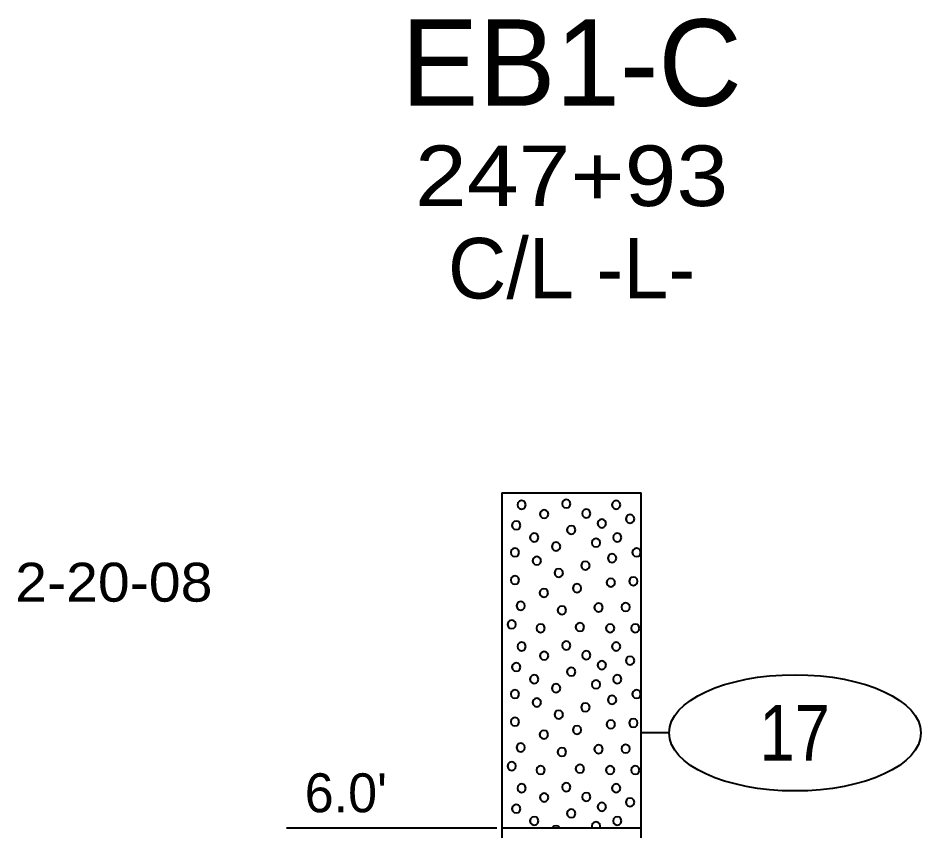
# Model space of a CAD drawing. Extents: x -76 to 974, y -1080 to -735.
# Drawn here: x -20.21 to -4.02, y -772.06 to -757.49 of the extents above; entities that cross this region are included whole.
import ezdxf
from ezdxf.enums import TextEntityAlignment as Align

# ---------------------------------------------------------------- set-up
doc = ezdxf.new("R2010")
doc.units = 0
doc.header["$LTSCALE"] = 0.36
doc.layers.add('27', color=7, linetype='Continuous', lineweight=40)

msp = doc.modelspace()

# ---------------------------------------------------------------- linework, layer by layer
at = {"layer": '27'}
for p, q in [((-11.5338, -766.0053), (-11.5338, -772.0053)), ((-11.5338, -766.0053), (-9.0338, -766.0053)), ((-9.0338, -772.0053), (-9.0338, -766.0053)), ((-8.5338, -770.3053), (-9.0338, -770.3053)), ((-15.39, -772.0053), (-11.6226, -772.0053)), ((-11.5338, -772.0053), (-9.0338, -772.0053)), ((-11.5338, -772.0053), (-11.5338, -778.0053)), ((-9.0338, -778.0053), (-9.0338, -772.0053))]:
    msp.add_line(p, q, dxfattribs=at)
for points in [[(-11.1019, -766.2179), (-11.1121, -766.1798), (-11.14, -766.1519), (-11.1781, -766.1417), (-11.2162, -766.1519), (-11.244, -766.1798), (-11.2543, -766.2179), (-11.244, -766.256), (-11.2162, -766.2839), (-11.1781, -766.2941), (-11.14, -766.2839), (-11.1121, -766.256)], [(-10.3009, -766.1983), (-10.3111, -766.1602), (-10.339, -766.1323), (-10.3771, -766.1221), (-10.4152, -766.1323), (-10.4431, -766.1602), (-10.4533, -766.1983), (-10.4431, -766.2364), (-10.4152, -766.2643), (-10.3771, -766.2745), (-10.339, -766.2643), (-10.3111, -766.2364)], [(-9.4072, -766.218), (-9.4174, -766.1799), (-9.4453, -766.152), (-9.4834, -766.1418), (-9.5215, -766.152), (-9.5494, -766.1799), (-9.5596, -766.218), (-9.5494, -766.2561), (-9.5215, -766.284), (-9.4834, -766.2942), (-9.4453, -766.284), (-9.4174, -766.2561)], [(-10.6969, -766.3832), (-10.7071, -766.3451), (-10.735, -766.3172), (-10.7731, -766.307), (-10.8112, -766.3172), (-10.8391, -766.3451), (-10.8493, -766.3832), (-10.8391, -766.4213), (-10.8112, -766.4492), (-10.7731, -766.4594), (-10.735, -766.4492), (-10.7071, -766.4213)], [(-9.9418, -766.3742), (-9.952, -766.3361), (-9.9799, -766.3082), (-10.018, -766.298), (-10.0561, -766.3082), (-10.084, -766.3361), (-10.0942, -766.3742), (-10.084, -766.4123), (-10.0561, -766.4402), (-10.018, -766.4504), (-9.9799, -766.4402), (-9.952, -766.4123)], [(-9.1564, -766.4701), (-9.1666, -766.432), (-9.1945, -766.4041), (-9.2326, -766.3939), (-9.2707, -766.4041), (-9.2986, -766.432), (-9.3088, -766.4701), (-9.2986, -766.5082), (-9.2707, -766.5361), (-9.2326, -766.5463), (-9.1945, -766.5361), (-9.1666, -766.5082)], [(-11.198, -766.5858), (-11.2082, -766.5477), (-11.2361, -766.5198), (-11.2742, -766.5096), (-11.3123, -766.5198), (-11.3402, -766.5477), (-11.3504, -766.5858), (-11.3402, -766.6239), (-11.3123, -766.6518), (-11.2742, -766.662), (-11.2361, -766.6518), (-11.2082, -766.6239)], [(-9.6636, -766.5514), (-9.6738, -766.5133), (-9.7017, -766.4854), (-9.7398, -766.4752), (-9.7779, -766.4854), (-9.8058, -766.5133), (-9.816, -766.5514), (-9.8058, -766.5895), (-9.7779, -766.6174), (-9.7398, -766.6276), (-9.7017, -766.6174), (-9.6738, -766.5895)], [(-10.8751, -766.8044), (-10.8853, -766.7663), (-10.9132, -766.7384), (-10.9513, -766.7282), (-10.9894, -766.7384), (-11.0173, -766.7663), (-11.0275, -766.8044), (-11.0173, -766.8425), (-10.9894, -766.8704), (-10.9513, -766.8806), (-10.9132, -766.8704), (-10.8853, -766.8425)], [(-10.2119, -766.669), (-10.2222, -766.6309), (-10.25, -766.603), (-10.2881, -766.5928), (-10.3262, -766.603), (-10.3541, -766.6309), (-10.3643, -766.669), (-10.3541, -766.7071), (-10.3262, -766.735), (-10.2881, -766.7452), (-10.25, -766.735), (-10.2222, -766.7071)], [(-9.3865, -766.8044), (-9.3967, -766.7663), (-9.4246, -766.7384), (-9.4627, -766.7282), (-9.5008, -766.7384), (-9.5287, -766.7663), (-9.5389, -766.8044), (-9.5287, -766.8425), (-9.5008, -766.8704), (-9.4627, -766.8806), (-9.4246, -766.8704), (-9.3967, -766.8425)], [(-10.4836, -766.9659), (-10.4938, -766.9278), (-10.5217, -766.8999), (-10.5598, -766.8897), (-10.5979, -766.8999), (-10.6258, -766.9278), (-10.636, -766.9659), (-10.6258, -767.004), (-10.5979, -767.0319), (-10.5598, -767.0421), (-10.5217, -767.0319), (-10.4938, -767.004)], [(-9.7678, -766.8972), (-9.7781, -766.8591), (-9.8059, -766.8312), (-9.844, -766.821), (-9.8821, -766.8312), (-9.91, -766.8591), (-9.9202, -766.8972), (-9.91, -766.9353), (-9.8821, -766.9632), (-9.844, -766.9734), (-9.8059, -766.9632), (-9.7781, -766.9353)], [(-11.2209, -767.0701), (-11.2311, -767.032), (-11.259, -767.0041), (-11.2971, -766.9939), (-11.3352, -767.0041), (-11.3631, -767.032), (-11.3733, -767.0701), (-11.3631, -767.1082), (-11.3352, -767.1361), (-11.2971, -767.1463), (-11.259, -767.1361), (-11.2311, -767.1082)], [(-9.0407, -767.0701), (-9.0509, -767.032), (-9.0788, -767.0041), (-9.1169, -766.9939), (-9.155, -767.0041), (-9.1829, -767.032), (-9.1931, -767.0701), (-9.1829, -767.1082), (-9.155, -767.1361), (-9.1169, -767.1463), (-9.0788, -767.1361), (-9.0509, -767.1082)], [(-10.8294, -767.2201), (-10.8396, -767.182), (-10.8675, -767.1541), (-10.9056, -767.1439), (-10.9437, -767.1541), (-10.9715, -767.182), (-10.9818, -767.2201), (-10.9715, -767.2582), (-10.9437, -767.2861), (-10.9056, -767.2963), (-10.8675, -767.2861), (-10.8396, -767.2582)], [(-9.4793, -767.1744), (-9.4895, -767.1363), (-9.5174, -767.1084), (-9.5555, -767.0982), (-9.5936, -767.1084), (-9.6215, -767.1363), (-9.6317, -767.1744), (-9.6215, -767.2125), (-9.5936, -767.2404), (-9.5555, -767.2506), (-9.5174, -767.2404), (-9.4895, -767.2125)], [(-10.4353, -767.4388), (-10.4455, -767.4007), (-10.4734, -767.3728), (-10.5115, -767.3626), (-10.5496, -767.3728), (-10.5775, -767.4007), (-10.5877, -767.4388), (-10.5775, -767.4769), (-10.5496, -767.5048), (-10.5115, -767.515), (-10.4734, -767.5048), (-10.4455, -767.4769)], [(-9.9573, -767.3078), (-9.9675, -767.2697), (-9.9954, -767.2419), (-10.0335, -767.2316), (-10.0716, -767.2419), (-10.0995, -767.2697), (-10.1097, -767.3078), (-10.0995, -767.3459), (-10.0716, -767.3738), (-10.0335, -767.384), (-9.9954, -767.3738), (-9.9675, -767.3459)], [(-11.2209, -767.5659), (-11.2311, -767.5278), (-11.259, -767.4999), (-11.2971, -767.4897), (-11.3352, -767.4999), (-11.3631, -767.5278), (-11.3733, -767.5659), (-11.3631, -767.604), (-11.3352, -767.6319), (-11.2971, -767.6421), (-11.259, -767.6319), (-11.2311, -767.604)], [(-9.5021, -767.613), (-9.5124, -767.5749), (-9.5402, -767.547), (-9.5783, -767.5368), (-9.6164, -767.547), (-9.6443, -767.5749), (-9.6545, -767.613), (-9.6443, -767.6511), (-9.6164, -767.6789), (-9.5783, -767.6892), (-9.5402, -767.6789), (-9.5124, -767.6511)], [(-9.0979, -767.5888), (-9.1081, -767.5507), (-9.136, -767.5228), (-9.1741, -767.5126), (-9.2122, -767.5228), (-9.2401, -767.5507), (-9.2503, -767.5888), (-9.2401, -767.6269), (-9.2122, -767.6548), (-9.1741, -767.665), (-9.136, -767.6548), (-9.1081, -767.6269)], [(-10.1073, -767.7134), (-10.1175, -767.6753), (-10.1454, -767.6474), (-10.1835, -767.6372), (-10.2216, -767.6474), (-10.2495, -767.6753), (-10.2597, -767.7134), (-10.2495, -767.7515), (-10.2216, -767.7794), (-10.1835, -767.7896), (-10.1454, -767.7794), (-10.1175, -767.7515)], [(-10.7022, -767.7973), (-10.7124, -767.7592), (-10.7403, -767.7313), (-10.7784, -767.7211), (-10.8165, -767.7313), (-10.8444, -767.7592), (-10.8546, -767.7973), (-10.8444, -767.8354), (-10.8165, -767.8633), (-10.7784, -767.8735), (-10.7403, -767.8633), (-10.7124, -767.8354)], [(-11.1179, -768.0287), (-11.1281, -767.9906), (-11.156, -767.9627), (-11.1941, -767.9525), (-11.2322, -767.9627), (-11.2601, -767.9906), (-11.2703, -768.0287), (-11.2601, -768.0668), (-11.2322, -768.0946), (-11.1941, -768.1049), (-11.156, -768.0946), (-11.1281, -768.0668)], [(-9.7221, -768.0579), (-9.7323, -768.0198), (-9.7602, -767.9919), (-9.7983, -767.9817), (-9.8364, -767.9919), (-9.8643, -768.0198), (-9.8745, -768.0579), (-9.8643, -768.096), (-9.8364, -768.1239), (-9.7983, -768.1341), (-9.7602, -768.1239), (-9.7323, -768.096)], [(-9.2365, -768.0503), (-9.2467, -768.0122), (-9.2746, -767.9843), (-9.3127, -767.9741), (-9.3508, -767.9843), (-9.3786, -768.0122), (-9.3889, -768.0503), (-9.3786, -768.0884), (-9.3508, -768.1163), (-9.3127, -768.1265), (-9.2746, -768.1163), (-9.2467, -768.0884)], [(-10.3793, -768.1087), (-10.3895, -768.0706), (-10.4174, -768.0428), (-10.4555, -768.0325), (-10.4936, -768.0428), (-10.5215, -768.0706), (-10.5317, -768.1087), (-10.5215, -768.1468), (-10.4936, -768.1747), (-10.4555, -768.1849), (-10.4174, -768.1747), (-10.3895, -768.1468)], [(-11.2794, -768.3617), (-11.2896, -768.3236), (-11.3175, -768.2957), (-11.3556, -768.2855), (-11.3937, -768.2957), (-11.4216, -768.3236), (-11.4318, -768.3617), (-11.4216, -768.3998), (-11.3937, -768.4277), (-11.3556, -768.4379), (-11.3175, -768.4277), (-11.2896, -768.3998)], [(-10.0564, -768.4088), (-10.0666, -768.3707), (-10.0945, -768.3428), (-10.1326, -768.3326), (-10.1707, -768.3428), (-10.1986, -768.3707), (-10.2088, -768.4088), (-10.1986, -768.4469), (-10.1707, -768.4748), (-10.1326, -768.485), (-10.0945, -768.4748), (-10.0666, -768.4469)], [(-10.7607, -768.4316), (-10.7709, -768.3935), (-10.7988, -768.3657), (-10.8369, -768.3554), (-10.875, -768.3657), (-10.9029, -768.3935), (-10.9131, -768.4316), (-10.9029, -768.4697), (-10.875, -768.4976), (-10.8369, -768.5078), (-10.7988, -768.4976), (-10.7709, -768.4697)], [(-9.5136, -768.4316), (-9.5238, -768.3935), (-9.5517, -768.3657), (-9.5898, -768.3554), (-9.6279, -768.3657), (-9.6558, -768.3935), (-9.666, -768.4316), (-9.6558, -768.4697), (-9.6279, -768.4976), (-9.5898, -768.5078), (-9.5517, -768.4976), (-9.5238, -768.4697)], [(-9.0636, -768.4316), (-9.0738, -768.3935), (-9.1017, -768.3657), (-9.1398, -768.3554), (-9.1779, -768.3657), (-9.2058, -768.3935), (-9.216, -768.4316), (-9.2058, -768.4697), (-9.1779, -768.4976), (-9.1398, -768.5078), (-9.1017, -768.4976), (-9.0738, -768.4697)], [(-10.3009, -768.7383), (-10.3111, -768.7002), (-10.339, -768.6723), (-10.3771, -768.6621), (-10.4152, -768.6723), (-10.4431, -768.7002), (-10.4533, -768.7383), (-10.4431, -768.7764), (-10.4152, -768.8043), (-10.3771, -768.8145), (-10.339, -768.8043), (-10.3111, -768.7764)], [(-11.1019, -768.7579), (-11.1121, -768.7198), (-11.14, -768.6919), (-11.1781, -768.6817), (-11.2162, -768.6919), (-11.244, -768.7198), (-11.2543, -768.7579), (-11.244, -768.796), (-11.2162, -768.8239), (-11.1781, -768.8341), (-11.14, -768.8239), (-11.1121, -768.796)], [(-9.4072, -768.758), (-9.4174, -768.7199), (-9.4453, -768.692), (-9.4834, -768.6818), (-9.5215, -768.692), (-9.5494, -768.7199), (-9.5596, -768.758), (-9.5494, -768.7961), (-9.5215, -768.824), (-9.4834, -768.8342), (-9.4453, -768.824), (-9.4174, -768.7961)], [(-10.6969, -768.9232), (-10.7071, -768.8851), (-10.735, -768.8572), (-10.7731, -768.847), (-10.8112, -768.8572), (-10.8391, -768.8851), (-10.8493, -768.9232), (-10.8391, -768.9613), (-10.8112, -768.9892), (-10.7731, -768.9994), (-10.735, -768.9892), (-10.7071, -768.9613)], [(-9.9418, -768.9142), (-9.952, -768.8761), (-9.9799, -768.8482), (-10.018, -768.838), (-10.0561, -768.8482), (-10.084, -768.8761), (-10.0942, -768.9142), (-10.084, -768.9523), (-10.0561, -768.9802), (-10.018, -768.9904), (-9.9799, -768.9802), (-9.952, -768.9523)], [(-9.1564, -769.0101), (-9.1666, -768.972), (-9.1945, -768.9441), (-9.2326, -768.9339), (-9.2707, -768.9441), (-9.2986, -768.972), (-9.3088, -769.0101), (-9.2986, -769.0482), (-9.2707, -769.0761), (-9.2326, -769.0863), (-9.1945, -769.0761), (-9.1666, -769.0482)], [(-11.198, -769.1258), (-11.2082, -769.0877), (-11.2361, -769.0598), (-11.2742, -769.0496), (-11.3123, -769.0598), (-11.3402, -769.0877), (-11.3504, -769.1258), (-11.3402, -769.1639), (-11.3123, -769.1918), (-11.2742, -769.202), (-11.2361, -769.1918), (-11.2082, -769.1639)], [(-10.2119, -769.209), (-10.2222, -769.1709), (-10.25, -769.143), (-10.2881, -769.1328), (-10.3262, -769.143), (-10.3541, -769.1709), (-10.3643, -769.209), (-10.3541, -769.2471), (-10.3262, -769.275), (-10.2881, -769.2852), (-10.25, -769.275), (-10.2222, -769.2471)], [(-9.6636, -769.0914), (-9.6738, -769.0533), (-9.7017, -769.0254), (-9.7398, -769.0152), (-9.7779, -769.0254), (-9.8058, -769.0533), (-9.816, -769.0914), (-9.8058, -769.1295), (-9.7779, -769.1574), (-9.7398, -769.1676), (-9.7017, -769.1574), (-9.6738, -769.1295)], [(-10.8751, -769.3444), (-10.8853, -769.3063), (-10.9132, -769.2784), (-10.9513, -769.2682), (-10.9894, -769.2784), (-11.0173, -769.3063), (-11.0275, -769.3444), (-11.0173, -769.3825), (-10.9894, -769.4104), (-10.9513, -769.4206), (-10.9132, -769.4104), (-10.8853, -769.3825)], [(-9.3865, -769.3444), (-9.3967, -769.3063), (-9.4246, -769.2784), (-9.4627, -769.2682), (-9.5008, -769.2784), (-9.5287, -769.3063), (-9.5389, -769.3444), (-9.5287, -769.3825), (-9.5008, -769.4104), (-9.4627, -769.4206), (-9.4246, -769.4104), (-9.3967, -769.3825)], [(-10.4836, -769.5059), (-10.4938, -769.4678), (-10.5217, -769.4399), (-10.5598, -769.4297), (-10.5979, -769.4399), (-10.6258, -769.4678), (-10.636, -769.5059), (-10.6258, -769.544), (-10.5979, -769.5719), (-10.5598, -769.5821), (-10.5217, -769.5719), (-10.4938, -769.544)], [(-9.7678, -769.4372), (-9.7781, -769.3991), (-9.8059, -769.3712), (-9.844, -769.361), (-9.8821, -769.3712), (-9.91, -769.3991), (-9.9202, -769.4372), (-9.91, -769.4753), (-9.8821, -769.5032), (-9.844, -769.5134), (-9.8059, -769.5032), (-9.7781, -769.4753)], [(-11.2209, -769.6101), (-11.2311, -769.572), (-11.259, -769.5441), (-11.2971, -769.5339), (-11.3352, -769.5441), (-11.3631, -769.572), (-11.3733, -769.6101), (-11.3631, -769.6482), (-11.3352, -769.6761), (-11.2971, -769.6863), (-11.259, -769.6761), (-11.2311, -769.6482)], [(-9.4793, -769.7144), (-9.4895, -769.6763), (-9.5174, -769.6484), (-9.5555, -769.6382), (-9.5936, -769.6484), (-9.6215, -769.6763), (-9.6317, -769.7144), (-9.6215, -769.7525), (-9.5936, -769.7804), (-9.5555, -769.7906), (-9.5174, -769.7804), (-9.4895, -769.7525)], [(-9.0407, -769.6101), (-9.0509, -769.572), (-9.0788, -769.5441), (-9.1169, -769.5339), (-9.155, -769.5441), (-9.1829, -769.572), (-9.1931, -769.6101), (-9.1829, -769.6482), (-9.155, -769.6761), (-9.1169, -769.6863), (-9.0788, -769.6761), (-9.0509, -769.6482)], [(-10.8294, -769.7601), (-10.8396, -769.722), (-10.8675, -769.6941), (-10.9056, -769.6839), (-10.9437, -769.6941), (-10.9715, -769.722), (-10.9818, -769.7601), (-10.9715, -769.7982), (-10.9437, -769.8261), (-10.9056, -769.8363), (-10.8675, -769.8261), (-10.8396, -769.7982)], [(-9.9573, -769.8478), (-9.9675, -769.8097), (-9.9954, -769.7819), (-10.0335, -769.7716), (-10.0716, -769.7819), (-10.0995, -769.8097), (-10.1097, -769.8478), (-10.0995, -769.8859), (-10.0716, -769.9138), (-10.0335, -769.924), (-9.9954, -769.9138), (-9.9675, -769.8859)], [(-10.4353, -769.9788), (-10.4455, -769.9407), (-10.4734, -769.9128), (-10.5115, -769.9026), (-10.5496, -769.9128), (-10.5775, -769.9407), (-10.5877, -769.9788), (-10.5775, -770.0169), (-10.5496, -770.0448), (-10.5115, -770.055), (-10.4734, -770.0448), (-10.4455, -770.0169)], [(-11.2209, -770.1059), (-11.2311, -770.0678), (-11.259, -770.0399), (-11.2971, -770.0297), (-11.3352, -770.0399), (-11.3631, -770.0678), (-11.3733, -770.1059), (-11.3631, -770.144), (-11.3352, -770.1719), (-11.2971, -770.1821), (-11.259, -770.1719), (-11.2311, -770.144)], [(-9.5021, -770.153), (-9.5124, -770.1149), (-9.5402, -770.087), (-9.5783, -770.0768), (-9.6164, -770.087), (-9.6443, -770.1149), (-9.6545, -770.153), (-9.6443, -770.1911), (-9.6164, -770.2189), (-9.5783, -770.2292), (-9.5402, -770.2189), (-9.5124, -770.1911)], [(-9.0979, -770.1288), (-9.1081, -770.0907), (-9.136, -770.0628), (-9.1741, -770.0526), (-9.2122, -770.0628), (-9.2401, -770.0907), (-9.2503, -770.1288), (-9.2401, -770.1669), (-9.2122, -770.1948), (-9.1741, -770.205), (-9.136, -770.1948), (-9.1081, -770.1669)], [(-10.7022, -770.3373), (-10.7124, -770.2992), (-10.7403, -770.2713), (-10.7784, -770.2611), (-10.8165, -770.2713), (-10.8444, -770.2992), (-10.8546, -770.3373), (-10.8444, -770.3754), (-10.8165, -770.4033), (-10.7784, -770.4135), (-10.7403, -770.4033), (-10.7124, -770.3754)], [(-10.1073, -770.2534), (-10.1175, -770.2153), (-10.1454, -770.1874), (-10.1835, -770.1772), (-10.2216, -770.1874), (-10.2495, -770.2153), (-10.2597, -770.2534), (-10.2495, -770.2915), (-10.2216, -770.3194), (-10.1835, -770.3296), (-10.1454, -770.3194), (-10.1175, -770.2915)], [(-11.1179, -770.5687), (-11.1281, -770.5306), (-11.156, -770.5027), (-11.1941, -770.4925), (-11.2322, -770.5027), (-11.2601, -770.5306), (-11.2703, -770.5687), (-11.2601, -770.6068), (-11.2322, -770.6346), (-11.1941, -770.6449), (-11.156, -770.6346), (-11.1281, -770.6068)], [(-10.3793, -770.6487), (-10.3895, -770.6106), (-10.4174, -770.5828), (-10.4555, -770.5725), (-10.4936, -770.5828), (-10.5215, -770.6106), (-10.5317, -770.6487), (-10.5215, -770.6868), (-10.4936, -770.7147), (-10.4555, -770.7249), (-10.4174, -770.7147), (-10.3895, -770.6868)], [(-9.7221, -770.5979), (-9.7323, -770.5598), (-9.7602, -770.5319), (-9.7983, -770.5217), (-9.8364, -770.5319), (-9.8643, -770.5598), (-9.8745, -770.5979), (-9.8643, -770.636), (-9.8364, -770.6639), (-9.7983, -770.6741), (-9.7602, -770.6639), (-9.7323, -770.636)], [(-9.2365, -770.5903), (-9.2467, -770.5522), (-9.2746, -770.5243), (-9.3127, -770.5141), (-9.3508, -770.5243), (-9.3786, -770.5522), (-9.3889, -770.5903), (-9.3786, -770.6284), (-9.3508, -770.6563), (-9.3127, -770.6665), (-9.2746, -770.6563), (-9.2467, -770.6284)], [(-11.2794, -770.9017), (-11.2896, -770.8636), (-11.3175, -770.8357), (-11.3556, -770.8255), (-11.3937, -770.8357), (-11.4216, -770.8636), (-11.4318, -770.9017), (-11.4216, -770.9398), (-11.3937, -770.9677), (-11.3556, -770.9779), (-11.3175, -770.9677), (-11.2896, -770.9398)], [(-10.7607, -770.9716), (-10.7709, -770.9335), (-10.7988, -770.9057), (-10.8369, -770.8954), (-10.875, -770.9057), (-10.9029, -770.9335), (-10.9131, -770.9716), (-10.9029, -771.0097), (-10.875, -771.0376), (-10.8369, -771.0478), (-10.7988, -771.0376), (-10.7709, -771.0097)], [(-10.0564, -770.9488), (-10.0666, -770.9107), (-10.0945, -770.8828), (-10.1326, -770.8726), (-10.1707, -770.8828), (-10.1986, -770.9107), (-10.2088, -770.9488), (-10.1986, -770.9869), (-10.1707, -771.0148), (-10.1326, -771.025), (-10.0945, -771.0148), (-10.0666, -770.9869)], [(-9.5136, -770.9716), (-9.5238, -770.9335), (-9.5517, -770.9057), (-9.5898, -770.8954), (-9.6279, -770.9057), (-9.6558, -770.9335), (-9.666, -770.9716), (-9.6558, -771.0097), (-9.6279, -771.0376), (-9.5898, -771.0478), (-9.5517, -771.0376), (-9.5238, -771.0097)], [(-9.0636, -770.9716), (-9.0738, -770.9335), (-9.1017, -770.9057), (-9.1398, -770.8954), (-9.1779, -770.9057), (-9.2058, -770.9335), (-9.216, -770.9716), (-9.2058, -771.0097), (-9.1779, -771.0376), (-9.1398, -771.0478), (-9.1017, -771.0376), (-9.0738, -771.0097)], [(-11.1019, -771.2979), (-11.1121, -771.2598), (-11.14, -771.2319), (-11.1781, -771.2217), (-11.2162, -771.2319), (-11.244, -771.2598), (-11.2543, -771.2979), (-11.244, -771.336), (-11.2162, -771.3639), (-11.1781, -771.3741), (-11.14, -771.3639), (-11.1121, -771.336)], [(-10.3009, -771.2783), (-10.3111, -771.2402), (-10.339, -771.2123), (-10.3771, -771.2021), (-10.4152, -771.2123), (-10.4431, -771.2402), (-10.4533, -771.2783), (-10.4431, -771.3164), (-10.4152, -771.3443), (-10.3771, -771.3545), (-10.339, -771.3443), (-10.3111, -771.3164)], [(-9.4072, -771.298), (-9.4174, -771.2599), (-9.4453, -771.232), (-9.4834, -771.2218), (-9.5215, -771.232), (-9.5494, -771.2599), (-9.5596, -771.298), (-9.5494, -771.3361), (-9.5215, -771.364), (-9.4834, -771.3742), (-9.4453, -771.364), (-9.4174, -771.3361)], [(-10.6969, -771.4632), (-10.7071, -771.4251), (-10.735, -771.3972), (-10.7731, -771.387), (-10.8112, -771.3972), (-10.8391, -771.4251), (-10.8493, -771.4632), (-10.8391, -771.5013), (-10.8112, -771.5292), (-10.7731, -771.5394), (-10.735, -771.5292), (-10.7071, -771.5013)], [(-9.9418, -771.4542), (-9.952, -771.4161), (-9.9799, -771.3882), (-10.018, -771.378), (-10.0561, -771.3882), (-10.084, -771.4161), (-10.0942, -771.4542), (-10.084, -771.4923), (-10.0561, -771.5202), (-10.018, -771.5304), (-9.9799, -771.5202), (-9.952, -771.4923)], [(-9.6636, -771.6314), (-9.6738, -771.5933), (-9.7017, -771.5654), (-9.7398, -771.5552), (-9.7779, -771.5654), (-9.8058, -771.5933), (-9.816, -771.6314), (-9.8058, -771.6695), (-9.7779, -771.6974), (-9.7398, -771.7076), (-9.7017, -771.6974), (-9.6738, -771.6695)], [(-9.1564, -771.5501), (-9.1666, -771.512), (-9.1945, -771.4841), (-9.2326, -771.4739), (-9.2707, -771.4841), (-9.2986, -771.512), (-9.3088, -771.5501), (-9.2986, -771.5882), (-9.2707, -771.6161), (-9.2326, -771.6263), (-9.1945, -771.6161), (-9.1666, -771.5882)], [(-11.198, -771.6658), (-11.2082, -771.6277), (-11.2361, -771.5998), (-11.2742, -771.5896), (-11.3123, -771.5998), (-11.3402, -771.6277), (-11.3504, -771.6658), (-11.3402, -771.7039), (-11.3123, -771.7318), (-11.2742, -771.742), (-11.2361, -771.7318), (-11.2082, -771.7039)], [(-10.2119, -771.749), (-10.2222, -771.7109), (-10.25, -771.683), (-10.2881, -771.6728), (-10.3262, -771.683), (-10.3541, -771.7109), (-10.3643, -771.749), (-10.3541, -771.7871), (-10.3262, -771.815), (-10.2881, -771.8252), (-10.25, -771.815), (-10.2222, -771.7871)], [(-10.8751, -771.8844), (-10.8853, -771.8463), (-10.9132, -771.8184), (-10.9513, -771.8082), (-10.9894, -771.8184), (-11.0173, -771.8463), (-11.0275, -771.8844), (-11.0173, -771.9225), (-10.9894, -771.9504), (-10.9513, -771.9606), (-10.9132, -771.9504), (-10.8853, -771.9225)], [(-9.7678, -771.9772), (-9.7781, -771.9391), (-9.8059, -771.9112), (-9.844, -771.901), (-9.8821, -771.9112), (-9.91, -771.9391), (-9.9202, -771.9772), (-9.9127, -772.0053), (-9.7754, -772.0053)], [(-9.3865, -771.8844), (-9.3967, -771.8463), (-9.4246, -771.8184), (-9.4627, -771.8082), (-9.5008, -771.8184), (-9.5287, -771.8463), (-9.5389, -771.8844), (-9.5287, -771.9225), (-9.5008, -771.9504), (-9.4627, -771.9606), (-9.4246, -771.9504), (-9.3967, -771.9225)], [(-10.5217, -771.9799), (-10.5598, -771.9697), (-10.5979, -771.9799), (-10.6233, -772.0053), (-10.4963, -772.0053)]]:
    msp.add_lwpolyline(points, close=True, dxfattribs=at)
msp.add_ellipse((-6.2764, -770.3053), major_axis=(2.2574, 0), ratio=0.461538, dxfattribs=at)

# ---------------------------------------------------------------- texts
for s, height, p in [('EB1-C', 1.55, (-10.2821, -759.0658)), ('C/L -L-', 1.085, (-10.2817, -762.5192))]:
    msp.add_text(s, height=height, dxfattribs=at).set_placement(p, align=Align.CENTER)
for s, height, width, p in [('247+93', 1.085, 1.15, (-10.2812, -760.8622)), ('2-20-08', 0.6976, 1.1, (-18.4882, -767.9537)), ('17', 1, 0.85, (-6.2838, -770.8052))]:
    msp.add_text(s, height=height, dxfattribs=dict(at, width=width)).set_placement(p, align=Align.CENTER)
msp.add_text("6.0'", height=0.6976, dxfattribs=at).set_placement((-15.066, -771.7289))

doc.saveas('drawing.dxf')
